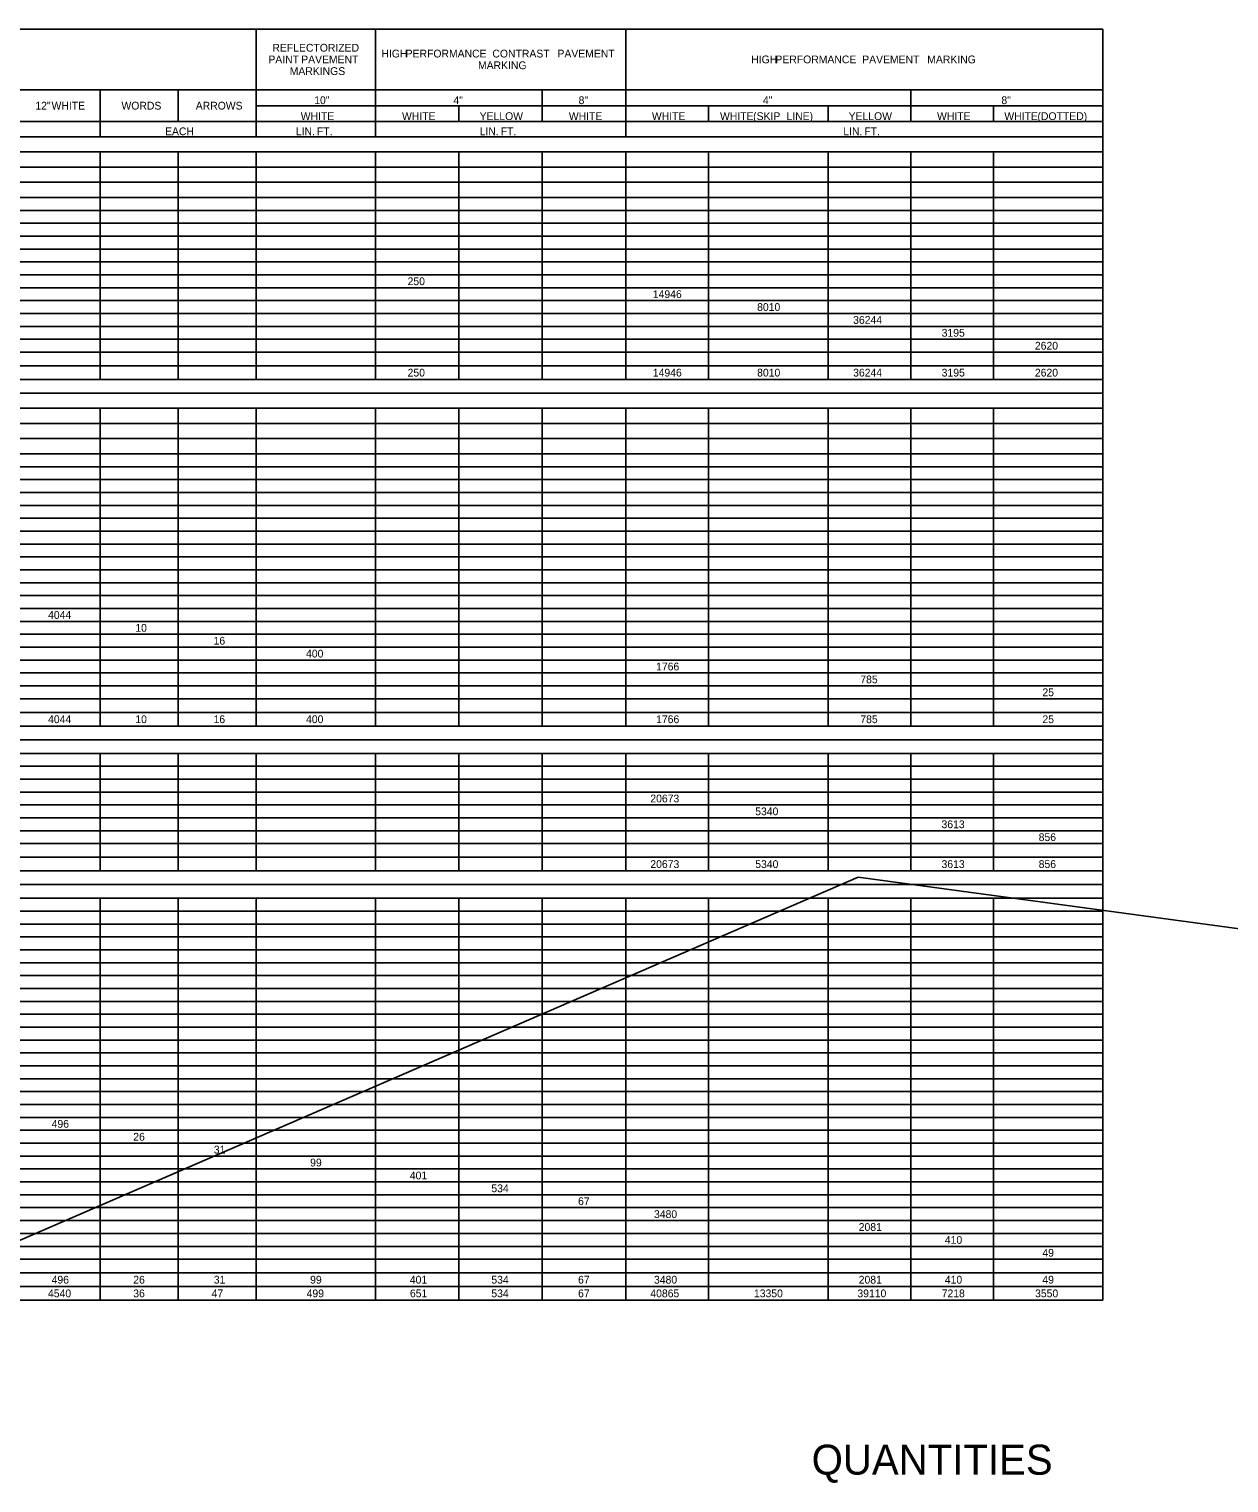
# Model space of a CAD drawing. Extents: x 1225909 to 1228704, y 151309 to 152305.
# Drawn here: x 1227705 to 1228204, y 151309 to 151915 of the extents above; entities that cross this region are included whole.
import ezdxf

# ---------------------------------------------------------------- set-up
doc = ezdxf.new("R2010")
doc.units = 0
for name, color, linetype in [('R_Border', 7, 'Continuous'), ('R_Border Notes', 7, 'Continuous'), ('R_Dimension', 7, 'Continuous')]:
    doc.layers.add(name, color=color, linetype=linetype)

msp = doc.modelspace()

# ---------------------------------------------------------------- linework, layer by layer
at = {"layer": 'R_Border'}
msp.add_lwpolyline([(1228341.02, 151522.17), (1228050.15, 151561.5), (1227672.06, 151397.84)], dxfattribs=at)
at = {"layer": 'R_Dimension'}
for p, q in [((1226577.42, 151914.54), (1228151.92, 151914.54)), ((1227799.61, 151869.71), (1227799.61, 151914.54)), ((1227849.17, 151869.71), (1227849.17, 151914.54)), ((1227953.35, 151869.71), (1227953.35, 151914.54)), ((1228151.92, 151385.44), (1228151.92, 151914.54)), ((1227345.33, 151889.28), (1228151.92, 151889.28)), ((1227734.58, 151869.71), (1227734.58, 151889.28)), ((1227767.09, 151876.02), (1227767.09, 151889.28)), ((1227799.61, 151889.28), (1227881.69, 151889.28)), ((1227849.17, 151889.28), (1228151.92, 151889.28)), ((1227918.62, 151876.02), (1227918.62, 151889.28)), ((1228072.05, 151876.02), (1228072.05, 151889.28)), ((1227799.61, 151882.65), (1228151.92, 151882.65)), ((1227849.17, 151876.02), (1227849.17, 151882.65)), ((1227883.9, 151876.02), (1227883.9, 151882.65)), ((1227987.76, 151876.02), (1227987.76, 151882.65)), ((1228037.64, 151876.02), (1228037.64, 151882.65)), ((1228106.46, 151876.02), (1228106.46, 151882.65)), ((1226750.73, 151876.02), (1228151.92, 151876.02)), ((1227702.06, 151876.02), (1228151.92, 151876.02)), ((1226577.42, 151869.71), (1228151.92, 151869.71)), ((1226577.42, 151863.4), (1228151.92, 151863.4)), ((1227734.58, 151768.69), (1227734.58, 151863.4)), ((1227767.09, 151768.69), (1227767.09, 151863.4)), ((1227799.61, 151768.69), (1227799.61, 151863.4)), ((1227849.17, 151768.69), (1227849.17, 151863.4)), ((1227883.9, 151768.69), (1227883.9, 151863.4)), ((1227918.62, 151768.69), (1227918.62, 151863.4)), ((1227953.35, 151768.69), (1227953.35, 151863.4)), ((1227987.76, 151768.69), (1227987.76, 151863.4)), ((1228037.64, 151768.69), (1228037.64, 151863.4)), ((1228072.05, 151768.69), (1228072.05, 151863.4)), ((1228106.46, 151768.69), (1228106.46, 151863.4)), ((1226577.42, 151857.08), (1228151.92, 151857.08)), ((1226577.42, 151850.77), (1228151.92, 151850.77)), ((1226577.42, 151844.45), (1228151.92, 151844.45)), ((1226577.42, 151839.09), (1228151.92, 151839.09)), ((1226577.42, 151833.72), (1228151.92, 151833.72)), ((1226577.42, 151828.35), (1228151.92, 151828.35)), ((1226577.42, 151822.99), (1228151.92, 151822.99)), ((1226577.42, 151817.62), (1228151.92, 151817.62)), ((1226577.42, 151812.25), (1228151.92, 151812.25)), ((1226577.42, 151806.89), (1228151.92, 151806.89)), ((1226577.42, 151801.52), (1228151.92, 151801.52)), ((1226577.42, 151796.15), (1228151.92, 151796.15)), ((1226577.42, 151790.79), (1228151.92, 151790.79)), ((1226577.42, 151785.42), (1228151.92, 151785.42)), ((1226577.42, 151780.05), (1228151.92, 151780.05)), ((1226577.42, 151774.37), (1228151.92, 151774.37)), ((1226577.42, 151768.69), (1228151.92, 151768.69)), ((1226577.42, 151763.01), (1228151.92, 151763.01)), ((1226577.42, 151756.69), (1228151.92, 151756.69)), ((1227734.58, 151624.42), (1227734.58, 151756.69)), ((1227767.09, 151624.42), (1227767.09, 151756.69)), ((1227799.61, 151624.42), (1227799.61, 151756.69)), ((1227849.17, 151624.42), (1227849.17, 151756.69)), ((1227883.9, 151624.42), (1227883.9, 151756.69)), ((1227918.62, 151624.42), (1227918.62, 151756.69)), ((1227953.35, 151624.42), (1227953.35, 151756.69)), ((1227987.76, 151624.42), (1227987.76, 151756.69)), ((1228037.64, 151624.42), (1228037.64, 151756.69)), ((1228072.05, 151624.42), (1228072.05, 151756.69)), ((1228106.46, 151624.42), (1228106.46, 151756.69)), ((1226577.42, 151750.38), (1228151.92, 151750.38)), ((1226577.42, 151744.07), (1228151.92, 151744.07)), ((1226577.42, 151737.75), (1228151.92, 151737.75)), ((1226577.42, 151732.39), (1228151.92, 151732.39)), ((1226577.42, 151727.02), (1228151.92, 151727.02)), ((1226577.42, 151721.65), (1228151.92, 151721.65)), ((1226577.42, 151716.29), (1228151.92, 151716.29)), ((1226577.42, 151710.92), (1228151.92, 151710.92)), ((1226577.42, 151705.55), (1228151.92, 151705.55)), ((1226577.42, 151700.18), (1228151.92, 151700.18)), ((1226577.42, 151694.82), (1228151.92, 151694.82)), ((1226577.42, 151689.45), (1228151.92, 151689.45)), ((1226577.42, 151684.08), (1228151.92, 151684.08)), ((1226577.42, 151678.72), (1228151.92, 151678.72)), ((1226577.42, 151673.35), (1228151.92, 151673.35)), ((1226577.42, 151667.98), (1228151.92, 151667.98)), ((1226577.42, 151662.62), (1228151.92, 151662.62)), ((1226577.42, 151657.25), (1228151.92, 151657.25)), ((1226577.42, 151651.88), (1228151.92, 151651.88)), ((1226577.42, 151646.52), (1228151.92, 151646.52)), ((1226577.42, 151641.15), (1228151.92, 151641.15)), ((1226577.42, 151635.78), (1228151.92, 151635.78)), ((1226577.42, 151630.1), (1228151.92, 151630.1)), ((1226577.42, 151624.42), (1228151.92, 151624.42)), ((1226577.42, 151618.74), (1228151.92, 151618.74)), ((1226577.42, 151613.05), (1228151.92, 151613.05)), ((1227734.58, 151564.12), (1227734.58, 151613.05)), ((1227767.09, 151564.12), (1227767.09, 151613.05)), ((1227799.61, 151564.12), (1227799.61, 151613.05)), ((1227849.17, 151564.12), (1227849.17, 151613.05)), ((1227883.9, 151564.12), (1227883.9, 151613.05)), ((1227918.62, 151564.12), (1227918.62, 151613.05)), ((1227953.35, 151564.12), (1227953.35, 151613.05)), ((1227987.76, 151564.12), (1227987.76, 151613.05)), ((1228037.64, 151564.12), (1228037.64, 151613.05)), ((1228072.05, 151564.12), (1228072.05, 151613.05)), ((1228106.46, 151564.12), (1228106.46, 151613.05)), ((1226577.42, 151607.69), (1228151.92, 151607.69)), ((1226577.42, 151602.32), (1228151.92, 151602.32)), ((1226577.42, 151596.95), (1228151.92, 151596.95)), ((1226577.42, 151591.59), (1228151.92, 151591.59)), ((1226577.42, 151586.22), (1228151.92, 151586.22)), ((1226577.42, 151580.85), (1228151.92, 151580.85)), ((1226577.42, 151575.49), (1228151.92, 151575.49)), ((1226577.42, 151569.81), (1228151.92, 151569.81)), ((1226577.42, 151564.12), (1228151.92, 151564.12)), ((1226577.42, 151558.44), (1228151.92, 151558.44)), ((1226577.42, 151552.76), (1228151.92, 151552.76)), ((1227734.58, 151385.44), (1227734.58, 151552.76)), ((1227767.09, 151385.44), (1227767.09, 151552.76)), ((1227799.61, 151385.44), (1227799.61, 151552.76)), ((1227849.17, 151385.44), (1227849.17, 151552.76)), ((1227883.9, 151385.44), (1227883.9, 151552.76)), ((1227918.62, 151385.44), (1227918.62, 151552.76)), ((1227953.35, 151385.44), (1227953.35, 151552.76)), ((1227987.76, 151385.44), (1227987.76, 151552.76)), ((1228037.64, 151385.44), (1228037.64, 151552.76)), ((1228072.05, 151385.44), (1228072.05, 151552.76)), ((1228106.46, 151385.44), (1228106.46, 151552.76)), ((1226577.42, 151547.39), (1228151.92, 151547.39)), ((1226577.42, 151542.02), (1228151.92, 151542.02)), ((1226577.42, 151536.66), (1228151.92, 151536.66)), ((1226577.42, 151531.29), (1228151.92, 151531.29)), ((1226577.42, 151525.92), (1228151.92, 151525.92)), ((1226577.42, 151520.56), (1228151.92, 151520.56)), ((1226577.42, 151515.19), (1228151.92, 151515.19)), ((1226577.42, 151509.82), (1228151.92, 151509.82)), ((1226577.42, 151504.46), (1228151.92, 151504.46)), ((1226577.42, 151499.09), (1228151.92, 151499.09)), ((1226577.42, 151493.72), (1228151.92, 151493.72)), ((1226577.42, 151488.36), (1228151.92, 151488.36)), ((1226577.42, 151482.99), (1228151.92, 151482.99)), ((1226577.42, 151477.62), (1228151.92, 151477.62)), ((1226577.42, 151472.26), (1228151.92, 151472.26)), ((1226577.42, 151466.89), (1228151.92, 151466.89)), ((1226577.42, 151461.52), (1228151.92, 151461.52)), ((1226577.42, 151456.16), (1228151.92, 151456.16)), ((1226577.42, 151450.79), (1228151.92, 151450.79)), ((1226577.42, 151445.42), (1228151.92, 151445.42)), ((1226577.42, 151440.06), (1228151.92, 151440.06)), ((1226577.42, 151434.69), (1228151.92, 151434.69)), ((1226577.42, 151429.32), (1228151.92, 151429.32)), ((1226577.42, 151423.96), (1228151.92, 151423.96)), ((1226577.42, 151418.59), (1228151.92, 151418.59)), ((1226577.42, 151413.22), (1228151.92, 151413.22)), ((1226577.42, 151407.86), (1228151.92, 151407.86)), ((1226577.42, 151402.49), (1228151.92, 151402.49)), ((1226577.42, 151396.81), (1228151.92, 151396.81)), ((1226577.42, 151391.13), (1228151.92, 151391.13)), ((1226577.42, 151385.44), (1228151.92, 151385.44))]:
    msp.add_line(p, q, dxfattribs=at)

# ---------------------------------------------------------------- texts
at = {"layer": 'R_Border Notes'}
msp.add_text('QUANTITIES', height=12.5, dxfattribs=at).set_placement((1228030.78, 151312.82))
at = {"layer": 'R_Dimension'}
for s, height, p in [('REFLECTORIZED', 3.2378, (1227806.3, 151905.15)), ('HIGH', 3.238, (1227851.69, 151902.72)), (' PERFORMANCE', 3.2378, (1227860.56, 151902.72)), (' CONTRAST', 3.238, (1227896.68, 151902.72)), (' PAVEMENT', 3.238, (1227923.76, 151902.72)), ('PAINT', 3.238, (1227804.62, 151900.29)), (' PAVEMENT', 3.238, (1227817.09, 151900.29)), ('MARKING', 3.238, (1227891.89, 151897.86)), ('HIGH', 3.238, (1228005.61, 151900.29)), (' PERFORMANCE', 3.2378, (1228014.48, 151900.29)), (' PAVEMENT', 3.238, (1228050.61, 151900.29)), (' MARKING', 3.238, (1228077.68, 151900.29)), ('MARKINGS', 3.238, (1227813.5, 151895.43)), ('12"', 3.238, (1227707.64, 151881.03)), (' WHITE', 3.238, (1227713.17, 151881.03)), ('WORDS', 3.238, (1227743.47, 151881.03)), ('ARROWS', 3.238, (1227774.4, 151881.03)), ('10"', 3.238, (1227823.71, 151883.3)), ('4"', 3.238, (1227881.67, 151883.3)), ('8"', 3.238, (1227933.76, 151883.3)), ('4"', 3.238, (1228010.47, 151883.3)), ('8"', 3.238, (1228109.75, 151883.3)), ('WHITE', 3.238, (1227818.09, 151876.67)), ('WHITE', 3.238, (1227860.24, 151876.67)), ('YELLOW', 3.238, (1227892.57, 151876.67)), ('WHITE', 3.238, (1227929.69, 151876.67)), ('WHITE', 3.238, (1227964.26, 151876.67)), ('WHITE', 3.238, (1227992.62, 151876.67)), (' (SKIP', 3.238, (1228005.22, 151876.67)), (' LINE)', 3.238, (1228019.08, 151876.67)), ('YELLOW', 3.238, (1228046.15, 151876.67)), ('WHITE', 3.238, (1228082.96, 151876.67)), ('WHITE', 3.238, (1228110.97, 151876.67)), (' (DOTTED)', 3.238, (1228123.57, 151876.67)), ('EACH', 3.238, (1227761.61, 151870.36)), ('LIN.', 3.238, (1227816.05, 151870.36)), (' FT.', 3.238, (1227823.6, 151870.36)), ('LIN.', 3.238, (1227892.58, 151870.36)), (' FT.', 3.238, (1227900.13, 151870.36)), ('LIN.', 3.238, (1228043.95, 151870.36)), (' FT.', 3.238, (1228051.5, 151870.36)), ('250', 3.238, (1227862.57, 151807.95)), ('14946', 3.238, (1227964.65, 151802.59)), ('8010', 3.238, (1228008.07, 151797.22)), ('36244', 3.238, (1228048.04, 151791.85)), ('3195', 3.238, (1228084.89, 151786.49)), ('2620', 3.238, (1228123.69, 151781.12)), ('250', 3.238, (1227862.57, 151769.91)), ('14946', 3.238, (1227964.65, 151769.91)), ('8010', 3.238, (1228008.07, 151769.91)), ('36244', 3.238, (1228048.04, 151769.91)), ('3195', 3.238, (1228084.89, 151769.91)), ('2620', 3.238, (1228123.69, 151769.91)), ('4044', 3.238, (1227712.91, 151669.05)), ('10', 3.238, (1227749.24, 151663.68)), ('16', 3.238, (1227781.81, 151658.32)), ('400', 3.238, (1227820.3, 151652.95)), ('1766', 3.238, (1227966.03, 151647.58)), ('785', 3.238, (1228051.02, 151642.22)), ('25', 3.238, (1228126.82, 151636.85)), ('4044', 3.238, (1227712.91, 151625.64)), ('10', 3.238, (1227749.24, 151625.64)), ('16', 3.238, (1227781.81, 151625.64)), ('400', 3.238, (1227820.3, 151625.64)), ('1766', 3.238, (1227966.03, 151625.64)), ('785', 3.238, (1228051.02, 151625.64)), ('25', 3.238, (1228126.82, 151625.64)), ('20673', 3.238, (1227963.62, 151592.65)), ('5340', 3.238, (1228007.28, 151587.29)), ('3613', 3.238, (1228084.82, 151581.92)), ('856', 3.238, (1228125.27, 151576.55)), ('20673', 3.238, (1227963.62, 151565.35)), ('5340', 3.238, (1228007.28, 151565.35)), ('3613', 3.238, (1228084.82, 151565.35)), ('856', 3.238, (1228125.27, 151565.35)), ('496', 3.238, (1227714.4, 151457.22)), ('26', 3.238, (1227748.37, 151451.85)), ('31', 3.238, (1227781.9, 151446.49)), ('99', 3.238, (1227822.01, 151441.12)), ('401', 3.238, (1227863.5, 151435.75)), ('534', 3.238, (1227897.44, 151430.39)), ('67', 3.238, (1227933.54, 151425.02)), ('3480', 3.238, (1227965.14, 151419.65)), ('2081', 3.238, (1228050.36, 151414.29)), ('410', 3.238, (1228086.21, 151408.92)), ('49', 3.238, (1228126.8, 151403.55)), ('496', 3.238, (1227714.4, 151392.35)), ('26', 3.238, (1227748.37, 151392.35)), ('31', 3.238, (1227781.9, 151392.35)), ('99', 3.238, (1227822.01, 151392.35)), ('401', 3.238, (1227863.5, 151392.35)), ('534', 3.238, (1227897.44, 151392.35)), ('67', 3.238, (1227933.54, 151392.35)), ('3480', 3.238, (1227965.14, 151392.35)), ('2081', 3.238, (1228050.36, 151392.35)), ('410', 3.238, (1228086.21, 151392.35)), ('49', 3.238, (1228126.8, 151392.35)), ('4540', 3.238, (1227712.9, 151386.66)), ('36', 3.238, (1227748.37, 151386.66)), ('47', 3.238, (1227780.98, 151386.66)), ('499', 3.238, (1227820.55, 151386.66)), ('651', 3.238, (1227863.55, 151386.66)), ('534', 3.238, (1227897.44, 151386.66)), ('67', 3.238, (1227933.54, 151386.66)), ('40865', 3.238, (1227963.62, 151386.66)), ('13350', 3.238, (1228006.75, 151386.66)), ('39110', 3.238, (1228049.81, 151386.66)), ('7218', 3.238, (1228084.89, 151386.66)), ('3550', 3.238, (1228123.77, 151386.66))]:
    msp.add_text(s, height=height, dxfattribs=at).set_placement(p)

doc.saveas('drawing.dxf')
